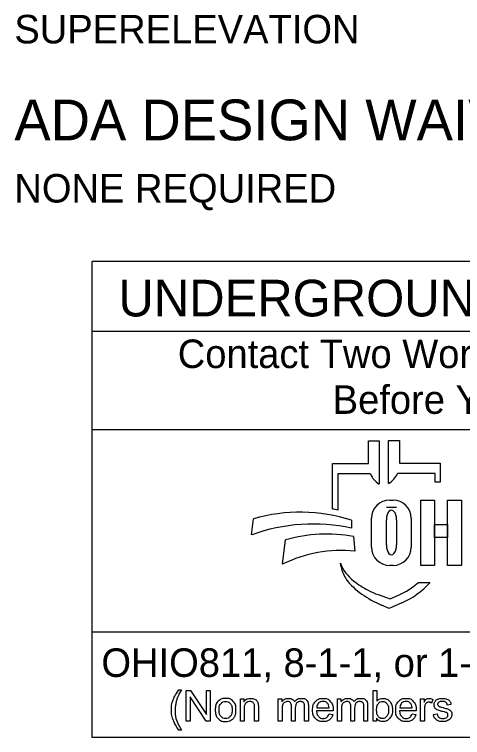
# Model space of a CAD drawing. Extents: x 0 to 34, y 0 to 22.
# Drawn here: x 1.995 to 4.196, y 1.843 to 5.393 of the extents above; entities that cross this region are included whole.
import ezdxf

# ---------------------------------------------------------------- set-up
doc = ezdxf.new("R2010")
doc.units = 0
doc.layers.add('SH_Data', color=7, linetype='Continuous')
doc.layers.add('SH_Text', color=7, linetype='Continuous')

msp = doc.modelspace()

# ---------------------------------------------------------------- linework, layer by layer
at = {"layer": 'SH_Data'}
for p, q in [((2.3775, 1.8428), (2.3775, 4.1803)), ((6.6275, 4.1803), (2.3775, 4.1803)), ((2.3775, 3.8387), (6.6275, 3.8387)), ((2.3775, 3.3553), (6.6275, 3.3553)), ((6.6275, 2.3607), (2.3775, 2.3607)), ((6.6275, 1.8428), (2.3775, 1.8428))]:
    msp.add_line(p, q, dxfattribs=at)
at = {"layer": 'SH_Text'}
for p, q in [((3.8329, 3.09), (3.8329, 3.3021)), ((3.8329, 3.3021), (3.8865, 3.3021)), ((3.8865, 3.3021), (3.8865, 3.1906)), ((3.7335, 3.1883), (3.7335, 3.2998)), ((3.7335, 3.2998), (3.7872, 3.2998)), ((3.7872, 3.2998), (3.7872, 3.0877)), ((3.5576, 2.9644), (3.5576, 3.1883)), ((3.5576, 3.1883), (3.7335, 3.1883)), ((3.8865, 3.1906), (4.0857, 3.1906)), ((4.0857, 3.1906), (4.0857, 3.0968)), ((3.5828, 3.1369), (3.5828, 2.96)), ((3.7439, 3.1369), (3.5828, 3.1369)), ((4.0625, 3.1392), (3.8761, 3.1392)), ((4.0625, 3.0968), (4.0625, 3.1392)), ((4.0857, 3.0968), (4.0625, 3.0968)), ((3.8385, 3.0091), (3.8551, 3.0091)), ((3.8718, 2.9721), (3.822, 2.9721)), ((3.1602, 2.8381), (3.1696, 2.9162)), ((3.7491, 2.7776), (3.7491, 2.9196)), ((3.822, 2.789), (3.822, 2.9114)), ((3.8718, 2.9114), (3.8718, 2.789)), ((3.9445, 2.9196), (3.9445, 2.7776)), ((3.6509, 2.9097), (3.6509, 2.8709)), ((3.312, 2.6936), (3.3267, 2.8137)), ((3.6608, 2.8291), (3.6671, 2.7582)), ((3.5997, 2.6807), (3.5967, 2.6986)), ((3.8551, 2.6882), (3.8385, 2.6882)), ((3.98, 2.6048), (4.0375, 2.6048)), ((3.7816, 2.5444), (3.841, 2.5239)), ((3.841, 2.5239), (3.8821, 2.5417)), ((3.835, 2.4769), (3.7976, 2.4934)), ((3.8983, 2.5044), (3.835, 2.4769))]:
    msp.add_line(p, q, dxfattribs=at)
for points in [[(3.991, 3.0081), (4.0589, 3.0081), (4.0589, 2.6881), (3.991, 2.6881)], [(4.1231, 3.0081), (4.1911, 3.0081), (4.1911, 2.6881), (4.1231, 2.6881)], [(4.0589, 2.8882), (4.1231, 2.8882), (4.1231, 2.8242), (4.0589, 2.8242)]]:
    msp.add_lwpolyline(points, close=True, dxfattribs=at)
for points in [[(2.8021, 2.0766), (2.8153, 2.0766)], [(2.8389, 1.9239), (2.8389, 2.0741), (2.8592, 2.0741), (2.9382, 1.9561), (2.9382, 2.0741), (2.9572, 2.0741), (2.9572, 1.9239), (2.9369, 1.9239), (2.8579, 2.0419), (2.8579, 1.9239), (2.8389, 1.9239)], [(3.7743, 1.9239), (3.7573, 1.9239), (3.7573, 2.0741), (3.7757, 2.0741), (3.7757, 2.0206)], [(3.1048, 1.9239), (3.1048, 2.0328), (3.1214, 2.0328), (3.1214, 2.0173)], [(3.2912, 1.9239), (3.2912, 2.0328), (3.3077, 2.0328), (3.3077, 2.0174)], [(3.5826, 1.9239), (3.5826, 2.0328), (3.5991, 2.0328), (3.5991, 2.0174)], [(3.9904, 1.9239), (3.9904, 2.0328), (4.007, 2.0328), (4.007, 2.0163)], [(4.0495, 2.0293), (4.043, 2.0122)], [(3.1932, 1.9908), (3.1932, 1.9239), (3.1748, 1.9239), (3.1748, 1.9901)], [(3.3743, 1.9871), (3.3743, 1.9239), (3.3559, 1.9239), (3.3559, 1.9946)], [(3.4388, 1.9986), (3.4388, 1.9239), (3.4203, 1.9239), (3.4203, 1.9924)], [(3.4799, 1.9887), (3.5406, 1.9887)], [(3.6657, 1.9871), (3.6657, 1.9239), (3.6473, 1.9239), (3.6473, 1.9946)], [(3.7301, 1.9986), (3.7301, 1.9239), (3.7117, 1.9239), (3.7117, 1.9924)], [(3.8879, 1.9887), (3.9486, 1.9887)], [(4.1394, 2.0046), (4.1213, 2.0022)], [(3.1233, 1.9833), (3.1233, 1.9239), (3.1048, 1.9239)], [(3.3097, 1.9803), (3.3097, 1.9239), (3.2912, 1.9239)], [(3.56, 1.9736), (3.4788, 1.9736)], [(3.5404, 1.9591), (3.5595, 1.9567)], [(3.601, 1.9803), (3.601, 1.9239), (3.5826, 1.9239)], [(3.968, 1.9736), (3.8868, 1.9736)], [(3.9484, 1.9591), (3.9675, 1.9567)], [(4.0088, 1.9809), (4.0088, 1.9239), (3.9904, 1.9239)], [(4.053, 1.9564), (4.0712, 1.9593)], [(3.7743, 1.9375), (3.7743, 1.9239)], [(2.8153, 1.8798), (2.8021, 1.8798)]]:
    msp.add_lwpolyline(points, dxfattribs=at)
for centre, radius, start, end in [((3.8353, 3.1736), 0.0985, 201.9296, 240.7469), ((3.7847, 3.176), 0.0985, 299.2531, 338.0704), ((3.8385, 2.9196), 0.0895, 90, 180), ((3.8551, 2.9196), 0.0895, 0, 90), ((3.3997, 2.1302), 0.8191, 72.1402, 106.3144), ((3.4295, 2.1554), 0.8191, 79.2074, 81.0007), ((3.4628, 1.9991), 0.8919, 77.8238, 109.8274), ((3.5267, 2.1094), 0.7322, 79.44, 105.8467), ((3.8385, 2.7776), 0.0895, 180, 270), ((3.8551, 2.7776), 0.0895, 270, 0), ((3.5987, 2.1262), 0.6357, 83.8248, 116.8021), ((3.7841, 2.7707), 0.2008, 201.0457, 232.5314), ((3.741, 2.7048), 0.1433, 189.6817, 216.0884), ((3.8747, 2.8022), 0.3088, 216.0884, 235.7167), ((3.9766, 3.0219), 0.5173, 232.5314, 241.794), ((3.7387, 2.8722), 0.3602, 293.4582, 312.0712), ((3.7387, 2.8722), 0.401, 293.4582, 317.8286), ((3.8914, 2.8631), 0.3371, 241.794, 250.9821), ((4.0412, 3.0465), 0.6044, 235.7167, 246.2325)]:
    msp.add_arc(centre, radius, start, end, dxfattribs=at)
for centre, start_param, end_param in [((3.8469, 2.9114), 4.712389, 7.853982), ((3.8469, 2.789), 1.570796, 4.712389)]:
    msp.add_ellipse(centre, major_axis=(0, 0.0484), ratio=0.514403, start_param=start_param, end_param=end_param, dxfattribs=at)
for points in [[(2.8021, 1.8798), (2.7869, 1.899), (2.7763, 1.9248), (2.7657, 1.9506), (2.7657, 1.9783), (2.7657, 2.0026), (2.7736, 2.025), (2.7829, 2.0509), (2.8021, 2.0766)], [(2.8153, 2.0766), (2.8029, 2.0553), (2.7989, 2.0462), (2.7927, 2.032), (2.7891, 2.0167), (2.7847, 1.9975), (2.7847, 1.9782), (2.7847, 1.9289), (2.8153, 1.8798)], [(2.9814, 1.9783), (2.9814, 2.0085), (2.9981, 2.0231), (3.0122, 2.0352), (3.0323, 2.0352), (3.0547, 2.0352), (3.069, 2.0205), (3.0832, 2.0058), (3.0832, 1.9799), (3.0832, 1.9589), (3.0769, 1.9469), (3.0706, 1.9348), (3.0586, 1.9282), (3.0466, 1.9215), (3.0323, 1.9215), (3.0095, 1.9215), (2.9954, 1.9362), (2.9814, 1.9508), (2.9814, 1.9783)], [(3.1214, 2.0173), (3.1334, 2.0352), (3.156, 2.0352), (3.1659, 2.0352), (3.1741, 2.0316), (3.1823, 2.0281), (3.1864, 2.0224), (3.1905, 2.0166), (3.1922, 2.0087), (3.1932, 2.0036), (3.1932, 1.9908)], [(3.3077, 2.0174), (3.3128, 2.0254), (3.3214, 2.0303), (3.3299, 2.0352), (3.3407, 2.0352), (3.3528, 2.0352), (3.3606, 2.0301), (3.3683, 2.0251), (3.3715, 2.0161), (3.3844, 2.0352), (3.4051, 2.0352), (3.4213, 2.0352), (3.43, 2.0262), (3.4388, 2.0172), (3.4388, 1.9986)], [(3.5595, 1.9567), (3.555, 1.94), (3.5428, 1.9307), (3.5306, 1.9215), (3.5117, 1.9215), (3.4878, 1.9215), (3.4738, 1.9362), (3.4598, 1.9509), (3.4598, 1.9774), (3.4598, 2.0049), (3.474, 2.02), (3.4881, 2.0352), (3.5106, 2.0352), (3.5324, 2.0352), (3.5463, 2.0203), (3.5601, 2.0055), (3.5601, 1.9785), (3.5601, 1.9769), (3.56, 1.9736)], [(3.5991, 2.0174), (3.6042, 2.0254), (3.6127, 2.0303), (3.6212, 2.0352), (3.6321, 2.0352), (3.6442, 2.0352), (3.6519, 2.0301), (3.6597, 2.0251), (3.6628, 2.0161), (3.6758, 2.0352), (3.6965, 2.0352), (3.7127, 2.0352), (3.7214, 2.0262), (3.7301, 2.0172), (3.7301, 1.9986)], [(3.7757, 2.0206), (3.7874, 2.0352), (3.8055, 2.0352), (3.8155, 2.0352), (3.8245, 2.0311), (3.8335, 2.0271), (3.8392, 2.0198), (3.845, 2.0124), (3.8483, 2.0021), (3.8516, 1.9918), (3.8516, 1.98), (3.8516, 1.952), (3.8378, 1.9368), (3.8239, 1.9215), (3.8046, 1.9215), (3.7853, 1.9215), (3.7743, 1.9375)], [(3.9675, 1.9567), (3.963, 1.94), (3.9508, 1.9307), (3.9386, 1.9215), (3.9196, 1.9215), (3.8958, 1.9215), (3.8818, 1.9362), (3.8678, 1.9509), (3.8678, 1.9774), (3.8678, 2.0049), (3.882, 2.02), (3.8961, 2.0352), (3.9186, 2.0352), (3.9404, 2.0352), (3.9543, 2.0203), (3.9681, 2.0055), (3.9681, 1.9785), (3.9681, 1.9769), (3.968, 1.9736)], [(4.007, 2.0163), (4.0133, 2.0278), (4.0187, 2.0315), (4.0241, 2.0352), (4.0305, 2.0352), (4.0398, 2.0352), (4.0495, 2.0293)], [(4.0712, 1.9593), (4.0727, 1.9483), (4.0798, 1.9425), (4.0868, 1.9366), (4.0995, 1.9366), (4.1122, 1.9366), (4.1184, 1.9418), (4.1245, 1.947), (4.1245, 1.954), (4.1245, 1.9602), (4.1191, 1.9638), (4.1153, 1.9663), (4.1002, 1.9701), (4.0799, 1.9752), (4.072, 1.9789), (4.0642, 1.9827), (4.0601, 1.9893), (4.0561, 1.9959), (4.0561, 2.0038), (4.0561, 2.0111), (4.0594, 2.0173), (4.0628, 2.0235), (4.0685, 2.0276), (4.0728, 2.0308), (4.0803, 2.033), (4.0877, 2.0352), (4.0962, 2.0352), (4.109, 2.0352), (4.1187, 2.0315), (4.1284, 2.0278), (4.133, 2.0215), (4.1377, 2.0152), (4.1394, 2.0046)], [(3.0003, 1.9783), (3.0003, 1.9574), (3.0094, 1.947), (3.0185, 1.9366), (3.0323, 1.9366), (3.046, 1.9366), (3.0551, 1.9471), (3.0642, 1.9575), (3.0642, 1.979), (3.0642, 1.9991), (3.0551, 2.0095), (3.0459, 2.0199), (3.0323, 2.0199), (3.0185, 2.0199), (3.0094, 2.0096), (3.0003, 1.9992), (3.0003, 1.9783)], [(3.1748, 1.9901), (3.1748, 2.0013), (3.1726, 2.0069), (3.1705, 2.0125), (3.165, 2.0158), (3.1595, 2.0191), (3.1521, 2.0191), (3.1404, 2.0191), (3.1318, 2.0117), (3.1233, 2.0042), (3.1233, 1.9833)], [(3.3559, 1.9946), (3.3559, 2.0069), (3.3514, 2.013), (3.3469, 2.0191), (3.3366, 2.0191), (3.3288, 2.0191), (3.3222, 2.015), (3.3156, 2.011), (3.3126, 2.0031), (3.3097, 1.9952), (3.3097, 1.9803)], [(3.4203, 1.9924), (3.4203, 2.0035), (3.4185, 2.0083), (3.4168, 2.0132), (3.412, 2.0162), (3.4073, 2.0191), (3.401, 2.0191), (3.3895, 2.0191), (3.3819, 2.0115), (3.3743, 2.0039), (3.3743, 1.9871)], [(3.5406, 1.9887), (3.5394, 2.0025), (3.5337, 2.0094), (3.5249, 2.0201), (3.5108, 2.0201), (3.4981, 2.0201), (3.4894, 2.0115), (3.4808, 2.003), (3.4799, 1.9887)], [(3.6473, 1.9946), (3.6473, 2.0069), (3.6428, 2.013), (3.6383, 2.0191), (3.628, 2.0191), (3.6202, 2.0191), (3.6136, 2.015), (3.607, 2.011), (3.604, 2.0031), (3.601, 1.9952), (3.601, 1.9803)], [(3.7117, 1.9924), (3.7117, 2.0035), (3.7099, 2.0083), (3.7081, 2.0132), (3.7034, 2.0162), (3.6987, 2.0191), (3.6923, 2.0191), (3.6809, 2.0191), (3.6733, 2.0115), (3.6657, 2.0039), (3.6657, 1.9871)], [(3.7741, 1.9792), (3.7741, 1.9596), (3.7794, 1.9509), (3.7881, 1.9366), (3.8029, 1.9366), (3.815, 1.9366), (3.8238, 1.9471), (3.8326, 1.9576), (3.8326, 1.9784), (3.8326, 1.9998), (3.8241, 2.0099), (3.8157, 2.0201), (3.8038, 2.0201), (3.7917, 2.0201), (3.7829, 2.0096), (3.7741, 1.999), (3.7741, 1.9792)], [(3.9486, 1.9887), (3.9474, 2.0025), (3.9417, 2.0094), (3.9328, 2.0201), (3.9188, 2.0201), (3.9061, 2.0201), (3.8974, 2.0115), (3.8888, 2.003), (3.8879, 1.9887)], [(4.043, 2.0122), (4.0363, 2.0162), (4.0295, 2.0162), (4.0235, 2.0162), (4.0187, 2.0125), (4.0139, 2.0089), (4.0119, 2.0024), (4.0088, 1.9926), (4.0088, 1.9809)], [(4.1213, 2.0022), (4.1201, 2.0106), (4.1142, 2.0153), (4.1083, 2.0201), (4.0975, 2.0201), (4.0848, 2.0201), (4.0794, 2.0159), (4.0739, 2.0116), (4.0739, 2.006), (4.0739, 2.0024), (4.0762, 1.9995), (4.0785, 1.9966), (4.0833, 1.9946), (4.086, 1.9936), (4.0996, 1.9899), (4.1192, 1.9847), (4.1269, 1.9813), (4.1347, 1.978), (4.1391, 1.9717), (4.1435, 1.9653), (4.1435, 1.9559), (4.1435, 1.9467), (4.1381, 1.9386), (4.1327, 1.9304), (4.1226, 1.926), (4.1124, 1.9215), (4.0996, 1.9215), (4.0784, 1.9215), (4.0672, 1.9303), (4.0561, 1.9391), (4.053, 1.9564)], [(3.4788, 1.9736), (3.4799, 1.9557), (3.489, 1.9462), (3.4981, 1.9366), (3.5117, 1.9366), (3.5219, 1.9366), (3.5291, 1.942), (3.5362, 1.9473), (3.5404, 1.9591)], [(3.8868, 1.9736), (3.8879, 1.9557), (3.897, 1.9462), (3.9061, 1.9366), (3.9197, 1.9366), (3.9299, 1.9366), (3.937, 1.942), (3.9442, 1.9473), (3.9484, 1.9591)]]:
    msp.add_open_spline(points, degree=3, dxfattribs=at)

# ---------------------------------------------------------------- texts
for s, height, p in [('SUPERELEVATION', 0.14, (1.9944, 5.2511)), ('ADA DESIGN WAIVERS', 0.2, (1.9944, 4.7753)), ('NONE REQUIRED', 0.14, (1.9944, 4.4698)), ('UNDERGROUND UTILITIES', 0.18, (2.5057, 3.9106)), ('Contact Two Working Days', 0.14, (2.7972, 3.6571)), ('Before You Dig', 0.14, (3.5583, 3.4321)), ('OHIO811, 8-1-1, or 1-800-362-2764', 0.14, (2.422, 2.1406))]:
    msp.add_text(s, height=height, dxfattribs=at).set_placement(p)

doc.saveas('drawing.dxf')
